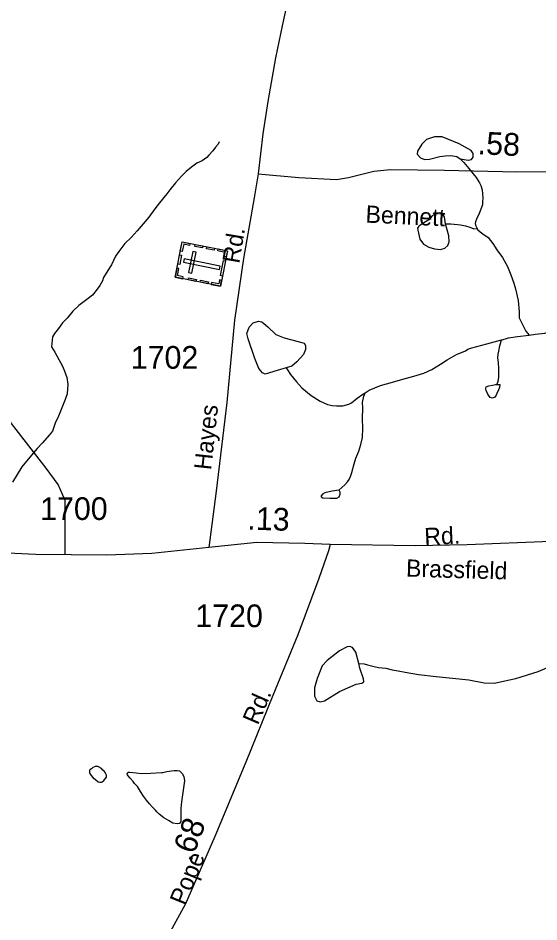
# Model space of a CAD drawing. Extents: x 2056842 to 2160602, y 826753 to 1016856.
# Drawn here: x 2104528 to 2107395, y 854986 to 859964 of the extents above; entities that cross this region are included whole.
import ezdxf

# ---------------------------------------------------------------- set-up
doc = ezdxf.new("R2010")
doc.units = 0
for name, color, linetype in [('Exist Cultural Cemetery CELL', 7, 'Continuous'), ('Exist Hydrographic Creek Single Shore', 7, 'Continuous'), ('Exist Hydrographic Misc Water Feature', 7, 'Continuous'), ('Exist Road Non-System Type 51', 7, 'Continuous'), ('Exist Road Secondary Mileage Hundredths English Label', 7, 'Continuous'), ('Exist Road Secondary Type 41 Attributed', 7, 'Continuous'), ('Exist Road Secondary Type 51 Attributed', 7, 'Continuous'), ('Exist Road Secondary Type 51 Label', 7, 'Continuous'), ('Exist Road Secondary Type 51 Number Label', 7, 'Continuous')]:
    doc.layers.add(name, color=color, linetype=linetype)

msp = doc.modelspace()

# ---------------------------------------------------------------- linework, layer by layer
at = {"layer": 'Exist Cultural Cemetery CELL'}
for points in [[(2105391.8, 858536.6), (2105430.4, 858731.8), (2105680.2, 858682.4), (2105641.6, 858487.1)], [(2105473, 858723.5), (2105470.8, 858712.4), (2105439.2, 858718.6), (2105431.3, 858678.8), (2105420.4, 858681), (2105430.5, 858731.9)], [(2105542.5, 858698.1), (2105500, 858706.5), (2105502.2, 858717.7), (2105544.7, 858709.3)], [(2105607.1, 858685.3), (2105564.6, 858693.7), (2105566.8, 858704.9), (2105609.3, 858696.4)], [(2105673.8, 858649.9), (2105662.5, 858652.1), (2105666.8, 858673.7), (2105627.2, 858681.5), (2105629.3, 858692.5), (2105680.2, 858682.4)], [(2105406.2, 858609.2), (2105416.2, 858660), (2105427.4, 858657.8), (2105417.4, 858607)], [(2105441.7, 858637.8), (2105438.1, 858619.5), (2105637, 858580.1), (2105640.6, 858598.4)], [(2105466.5, 858563.4), (2105484.8, 858559.7), (2105507.7, 858675.2), (2105489.3, 858678.9)], [(2105434.3, 858528.1), (2105436.5, 858539.3), (2105404.9, 858545.5), (2105412.8, 858585.3), (2105401.9, 858587.5), (2105391.8, 858536.6)], [(2105641.5, 858545.7), (2105657.9, 858628.9), (2105669.1, 858626.7), (2105652.6, 858543.5)], [(2105507, 858513.7), (2105464.5, 858522.1), (2105466.7, 858533.3), (2105509.2, 858524.9)], [(2105572.9, 858500.6), (2105530.5, 858509.1), (2105532.7, 858520.2), (2105575.2, 858511.8)], [(2105647.9, 858519.5), (2105636.7, 858521.8), (2105632.4, 858500.2), (2105592.7, 858508), (2105590.6, 858497.1), (2105641.5, 858487)]]:
    msp.add_lwpolyline(points, close=True, dxfattribs=at)
at = {"layer": 'Exist Hydrographic Creek Single Shore'}
msp.add_lwpolyline([(2105634.1, 859281.8), (2105630, 859269.5), (2105614.6, 859253.6), (2105600.1, 859233.4), (2105578.3, 859209.5), (2105566.2, 859195.6), (2105540.8, 859177.5), (2105512.3, 859165.2), (2105482.8, 859143.3), (2105452.9, 859119), (2105426.8, 859092.9), (2105394.8, 859056.8), (2105363, 859019), (2105347, 858996.7), (2105305.4, 858946.6), (2105279.6, 858912.8), (2105247.4, 858868.5), (2105205.6, 858818.5), (2105183.8, 858792.6), (2105149.8, 858756.3), (2105116, 858722.1), (2105082.3, 858678.1), (2105064.1, 858652.1), (2105042.3, 858605.9), (2105022, 858574), (2104998.7, 858535.7), (2104992.3, 858517.7), (2104978.6, 858491.8), (2104957, 858463.8), (2104936.9, 858437.6), (2104907, 858413.7), (2104862.9, 858381.4), (2104829.1, 858349.3), (2104797.3, 858311.1), (2104771.3, 858285), (2104749.7, 858255), (2104727.6, 858227.1), (2104717.3, 858209.1), (2104712, 858153.2), (2104729.8, 858123.3), (2104752, 858083), (2104770, 858051.1), (2104781.9, 858025.3), (2104796.1, 857985.4), (2104802.4, 857947.1), (2104798.5, 857895.4), (2104786.4, 857863.5), (2104765.1, 857809.1), (2104747.3, 857763.2), (2104732.9, 857739), (2104717.1, 857689), (2104699.3, 857666.9), (2104661.4, 857624.9), (2104631.8, 857592.8), (2104591.8, 857546.5), (2104548, 857492.7), (2104496.1, 857408.5)], dxfattribs=at)
at = {"layer": 'Exist Hydrographic Misc Water Feature'}
for points in [[(2106961.6, 859189.9), (2107004.6, 859181.2), (2107023.6, 859185), (2107033.7, 859198.9), (2107033.7, 859217.9), (2107021.1, 859235.6), (2106955.2, 859272.4), (2106861.5, 859310.4), (2106819.8, 859310.4), (2106775.4, 859295.2), (2106750.1, 859269.8), (2106727.3, 859231.8), (2106724.8, 859214.1), (2106742.5, 859195.1), (2106765.3, 859185), (2106793.2, 859187.5), (2106848.9, 859201.4), (2106879.3, 859205.2), (2106909.7, 859206.5), (2106942.6, 859202.7), (2106961.6, 859189.9)], [(2106961.6, 859189.9), (2106982.3, 859168.1), (2107008.4, 859136.1), (2107048.6, 859086.2), (2107068.5, 859056), (2107074.8, 859042.1), (2107082.6, 859018.2), (2107086.7, 858974.1), (2107084.9, 858952.1), (2107085.1, 858936.2), (2107065.2, 858888.1), (2107051.4, 858856.1), (2107045.3, 858842), (2107043.2, 858832.2), (2107045.3, 858824.2), (2107055.5, 858804.4)], [(2106880.5, 858831.7), (2106875.5, 858869.9), (2106864.1, 858886.3), (2106850.2, 858891.4), (2106833.7, 858890.1), (2106807.1, 858874.9), (2106788.1, 858853.4), (2106761.5, 858835.7), (2106733.7, 858817.9), (2106727.3, 858807.8), (2106728.6, 858796.4), (2106740, 858745.7), (2106759, 858719.1), (2106788.1, 858702.6), (2106819.8, 858692.5), (2106852.7, 858690), (2106876.7, 858696.3), (2106893.2, 858711.5), (2106900.8, 858731.8), (2106898.3, 858764.7), (2106880.5, 858831.7)], [(2106880.5, 858831.7), (2106891.3, 858831.7), (2106909.3, 858831.8), (2106929.2, 858829.6), (2106947.3, 858827.7), (2106963.1, 858826.1), (2106991.4, 858820.2), (2107015.1, 858812.1), (2107037.3, 858804.3), (2107055.5, 858804.4)], [(2107055.5, 858804.4), (2107057.4, 858800.1), (2107071.1, 858786.2), (2107085.3, 858776.3), (2107115.6, 858756.3), (2107141.7, 858722.3), (2107163.8, 858688.6), (2107193.7, 858644.7), (2107221.8, 858596.6), (2107240.3, 858550.8), (2107256.5, 858504.9), (2107266.3, 858473), (2107280.3, 858408.8), (2107287, 858346.9), (2107286.8, 858312.9), (2107323.1, 858239.2), (2107341, 858217)], [(2106003.8, 858037), (2105953.7, 858023.6), (2105887.9, 858003.3), (2105873.9, 858009.6), (2105852.4, 858035), (2105830.9, 858089.4), (2105794.2, 858198.4), (2105787.8, 858227.5), (2105799.2, 858261.7), (2105822, 858285.8), (2105851.1, 858294.7), (2105870.1, 858290.9), (2105901.8, 858264.3), (2105947.4, 858221.2), (2105991.7, 858202.2), (2106061.3, 858184.5), (2106103.1, 858174.3), (2106109.4, 858161.7), (2106109.4, 858138.9), (2106098, 858111), (2106062.6, 858070.4), (2106034.7, 858047.6), (2106003.8, 858037)], [(2107341, 858217), (2107376.9, 858223.3), (2107427.3, 858229.5), (2107465, 858239.6), (2107522.9, 858247.9), (2107581.1, 858255.7), (2107664.5, 858264.2), (2107748.6, 858266.4), (2107782.9, 858264.5), (2107814.8, 858262.5), (2107842.5, 858258.7), (2107856.9, 858252.9)], [(2106438.5, 857900.5), (2106460.3, 857914.6), (2106492.1, 857928.5), (2106522, 857940.6), (2106556, 857948.8), (2106602.2, 857962.9), (2106645.8, 857975), (2106705.9, 857991.1), (2106762.1, 858009.3), (2106805.8, 858029.5), (2106853.8, 858057.5), (2106889.7, 858081.7), (2106941.5, 858112), (2106991.6, 858132), (2107003, 858140), (2107025.4, 858148.4), (2107107.6, 858170.4), (2107149.2, 858180.8), (2107189, 858192.5)], [(2107163.8, 857946.8), (2107167.9, 857958.8), (2107171.6, 857970.8), (2107173.9, 857988.7), (2107174.1, 858002.5), (2107173.9, 858034.6), (2107171.6, 858066.6), (2107169.3, 858092.5), (2107171.4, 858112.5), (2107173.4, 858128.8), (2107179.2, 858158.8), (2107187.4, 858184.7), (2107189, 858192.5)], [(2107189, 858192.5), (2107193.3, 858192.7), (2107227.4, 858202.6), (2107277.2, 858210.8), (2107341, 858217)], [(2106003.8, 858037), (2106010, 858027.1), (2106028.2, 858001.2), (2106060.2, 857961.1), (2106090.2, 857927.3), (2106140.6, 857885.6), (2106190.6, 857853.7), (2106230.4, 857835.9), (2106256.7, 857829.9), (2106280.6, 857827.9), (2106314.7, 857828), (2106348.5, 857838.3), (2106362.3, 857844.3), (2106394.2, 857870.3), (2106426, 857892.2), (2106438.5, 857900.5)], [(2107163.8, 857946.8), (2107174.1, 857946.5), (2107180, 857946.8), (2107178.4, 857928.8), (2107172, 857916.8), (2107162.4, 857896.8), (2107160.1, 857886.5), (2107152.1, 857876.8), (2107140, 857870.5), (2107126.3, 857874.6), (2107118.1, 857886.4), (2107112.1, 857896.7), (2107104.1, 857912.4), (2107102.1, 857920.5), (2107102.3, 857926.5), (2107104.1, 857932.3), (2107119.9, 857938.5), (2107140.2, 857942.3), (2107156.2, 857946.8), (2107163.8, 857946.8)], [(2106293, 857363.5), (2106325.6, 857394.2), (2106342, 857410), (2106349.7, 857422.2), (2106357.5, 857440.1), (2106365.5, 857460.4), (2106377.8, 857508.4), (2106387.3, 857540.2), (2106403.1, 857578.4), (2106415.4, 857616.3), (2106423, 857654.5), (2106425, 857704.6), (2106423, 857756.4), (2106424.8, 857818.2), (2106424.4, 857846.3), (2106430.3, 857882.3), (2106438.5, 857900.5)], [(2106293, 857363.5), (2106257.6, 857358.4), (2106217.1, 857349.6), (2106203.1, 857342), (2106195.5, 857333.1), (2106195.5, 857326.8), (2106205.7, 857321.7), (2106243.7, 857320.4), (2106282.9, 857320.4), (2106295.6, 857326.8), (2106300.6, 857342), (2106300.6, 857353.4), (2106296.8, 857361), (2106293, 857363.5)], [(2106403.4, 856409.3), (2106387, 856471.3), (2106369.2, 856497.9), (2106354, 856503), (2106338.9, 856500.5), (2106297.1, 856478.9), (2106230, 856425.7), (2106202.1, 856396.6), (2106174.3, 856326.9), (2106159.1, 856275), (2106159.1, 856229.4), (2106173, 856204), (2106190.7, 856197.7), (2106214.8, 856204), (2106297.1, 856254.7), (2106389.5, 856295.2), (2106419.9, 856301.6), (2106431.3, 856307.9), (2106430, 856324.4), (2106409.8, 856383.9), (2106403.4, 856409.3)], [(2106403.4, 856409.3), (2106432.8, 856406.6), (2106450.8, 856402.6), (2106488.6, 856392.8), (2106511.1, 856387), (2106553, 856383.1), (2106586.8, 856375.1), (2106620.6, 856369.2), (2106659.4, 856361.3), (2106732.6, 856348.4), (2106830.1, 856338.3), (2107008.7, 856319.3), (2107093.5, 856302.8), (2107150.5, 856300.3), (2107223.1, 856317.3), (2107267.4, 856327.2), (2107391, 856365.7), (2107541.7, 856429.9)], [(2104991.3, 855758.3), (2104999.1, 855764.4), (2105007.1, 855774.2), (2105015.3, 855782.3), (2105015.1, 855786.3), (2105015.1, 855794.4), (2105012.8, 855798.4), (2105011.4, 855802.3), (2105006.9, 855808.2), (2105000.9, 855816.4), (2104994.8, 855822.3), (2104986.8, 855830.4), (2104971, 855840.1), (2104967.1, 855842.3), (2104962.8, 855842.1), (2104956.8, 855842.2), (2104952.9, 855842), (2104948.8, 855840.2), (2104938.8, 855836), (2104931, 855829.9), (2104922.8, 855823.8), (2104920.7, 855820.1), (2104920.7, 855814), (2104920.9, 855807.9), (2104922.8, 855803.9), (2104929.4, 855792), (2104941, 855780.1), (2104953.3, 855770.1), (2104969.1, 855758), (2104977.3, 855756.3), (2104983.3, 855756.3), (2104987.2, 855756.1), (2104991.3, 855758.3)], [(2105283.9, 855601.1), (2105265.4, 855618.9), (2105251.1, 855636.9), (2105235.3, 855657.2), (2105217.2, 855679), (2105201.3, 855705), (2105185.3, 855730.9), (2105169.1, 855748.8), (2105160.9, 855758.9), (2105145.3, 855776.8), (2105133.2, 855790.8), (2105129.1, 855796.7), (2105128.9, 855800.8), (2105131.1, 855806.5), (2105134.8, 855810.8), (2105140.8, 855810.7), (2105177.1, 855806.8), (2105204.7, 855803), (2105258.7, 855805), (2105319, 855809.3), (2105324.9, 855809.2), (2105346.8, 855813.6), (2105372.9, 855817.3), (2105386.8, 855819.7), (2105402.6, 855819.3), (2105416.8, 855817.6), (2105430.9, 855803.6), (2105440.5, 855787.6), (2105443, 855763.7), (2105438.9, 855723.7), (2105433.4, 855685.6), (2105427.4, 855647.5), (2105423.3, 855609.7), (2105423.5, 855587.7), (2105423.5, 855569.5), (2105423.5, 855557.7), (2105423.5, 855539.8), (2105415.5, 855527.6), (2105403.8, 855525.4), (2105379.9, 855529.4), (2105355.9, 855543.6), (2105329.6, 855559.3), (2105303.6, 855579.1), (2105291.9, 855593), (2105283.9, 855601.1)]]:
    msp.add_lwpolyline(points, dxfattribs=at)
at = {"layer": 'Exist Road Non-System Type 51'}
msp.add_lwpolyline([(2104786, 857007.9), (2104786, 857182.5), (2104786, 857307.2), (2104748.7, 857394.5), (2104682.2, 857486), (2104491.1, 857731.2), (2104428.8, 857855.9), (2104383.1, 857997.3), (2104395.6, 858117.8), (2104438.1, 858283), (2104450.6, 858353.7), (2104436.1, 858420.2), (2104380, 858511.7), (2104124.5, 858765.2)], dxfattribs=at)
at = {"layer": 'Exist Road Secondary Type 41 Attributed'}
msp.add_lwpolyline([(2105849.8, 859105.6), (2106073.1, 859086.9), (2106281.3, 859074.9), (2106345.7, 859085.3), (2106486.9, 859120.7), (2106577.2, 859131.1), (2106874.2, 859126.9), (2107273, 859116.5), (2107629.2, 859119.6), (2107708.1, 859140.4), (2107851.4, 859219.4), (2108005.1, 859304.6), (2108067.4, 859331.6), (2108150.5, 859389.8), (2108308.3, 859458.4), (2108565.9, 859556.1), (2108697.4, 859608.5), (2108790.9, 859661.7)], dxfattribs=at)
at = {"layer": 'Exist Road Secondary Type 51 Attributed'}
for points in [[(2105876.5, 864701), (2105881.4, 864661), (2105898.6, 864556.6), (2105941.2, 863784.5), (2105957.8, 863472.7), (2105972.3, 863179.7), (2105996.2, 863016.5), (2106060.6, 862713.1), (2106240.2, 861805.9), (2106283.8, 861571), (2106296.3, 861423.5), (2106275.5, 861269.7), (2106174.8, 860805.2), (2106100, 860468.5), (2105980.6, 859920.8), (2105945.3, 859746.2), (2105901.7, 859505.2), (2105874.7, 859326.4), (2105849.8, 859105.6)], [(2105849.8, 859105.6), (2105828, 858974.1), (2105767.7, 858639.5), (2105718.9, 858299.7), (2105677.4, 857846.6), (2105618.2, 857359.3), (2105578.5, 857049)], [(2108633.4, 857122.7), (2108577.8, 857124.7), (2108370.8, 857123.7), (2108114, 857106.5), (2107460, 857082), (2107000.5, 857062.4), (2106714, 857057.6), (2106245.9, 857063.8)], [(2105578.5, 857049), (2105264.6, 857015.8), (2105015.4, 857005.4), (2104622.8, 857009.6), (2104090.1, 857035.6), (2103984.2, 857029.3), (2103662.3, 856892.2), (2103489.9, 856823.6), (2103236.5, 856771.6), (2102965.5, 856716.5), (2102755.7, 856708.2), (2102533.5, 856706.1), (2102377.7, 856751.9), (2102217.8, 856787.2), (2102093.2, 856805.9), (2101999.7, 856787.2), (2101852.3, 856733.2), (2101620.7, 856667.7), (2101246.8, 856626.1), (2100713.3, 856564.4)], [(2106245.9, 857063.8), (2106236.6, 857029.8), (2106183.1, 856876.6), (2106067.3, 856567.4), (2105929.2, 856233.8), (2105781.2, 855865.4), (2105611.5, 855455.5), (2105448.9, 855085), (2105362.8, 854927.1), (2105251.1, 854764.4), (2104968.1, 854436.6), (2104675.8, 854108.7), (2104531, 853939.9)], [(2106245.9, 857063.8), (2106105.5, 857070), (2105841.1, 857075.8), (2105578.5, 857049)]]:
    msp.add_lwpolyline(points, dxfattribs=at)

# ---------------------------------------------------------------- texts
at = {"layer": 'Exist Road Secondary Mileage Hundredths English Label'}
for s, rotation, p in [('.58', 357.2814, (2107055.9, 859215.1)), ('.13', 358.2954, (2105788.4, 857146.8)), ('.68', 69.1405, (2105479.8, 855311))]:
    msp.add_text(s, height=125, rotation=rotation, dxfattribs=at).set_placement(p)
at = {"layer": 'Exist Road Secondary Type 51 Label'}
for s, rotation, p in [('Bennett', 357.2814, (2106438.9, 858838)), ('Rd.', 80.4326, (2105744.9, 858608.9)), ('Hayes', 83.7662, (2105590.3, 857472.1)), ('Rd.', 2.658, (2106766.1, 857060.4)), ('Brassfield', 358.3399, (2106662.3, 856888.1)), ('Rd.', 66.5718, (2105847.1, 856066)), ('Pope', 67.9137, (2105447.2, 855071.5))]:
    msp.add_text(s, height=95, rotation=rotation, dxfattribs=at).set_placement(p)
at = {"layer": 'Exist Road Secondary Type 51 Number Label'}
for s, p in [('1702', (2105148, 858032.9)), ('1700', (2104649, 857199.8)), ('1720', (2105503.4, 856609.4))]:
    msp.add_text(s, height=125, dxfattribs=at).set_placement(p)

doc.saveas('drawing.dxf')
